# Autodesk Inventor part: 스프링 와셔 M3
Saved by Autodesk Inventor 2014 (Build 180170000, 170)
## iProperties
Created: 2025-09
Part Number: 스프링 와셔 M3
Material: 일반
Document SubType Name: Modeling
Designer: dg
Density: 1 g/cm^3
Appearance: 기본값
Author: dg
Author: jhkim
Description: 스프링 잠금 와셔
Creation Date: 2025-09-02
Sending System: Autodesk Inventor 2026
Preprocessor: ST-DEVELOPER v20.1
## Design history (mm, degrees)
node "스프링 와셔 M31"
body "Solid1"
node "기준1"
